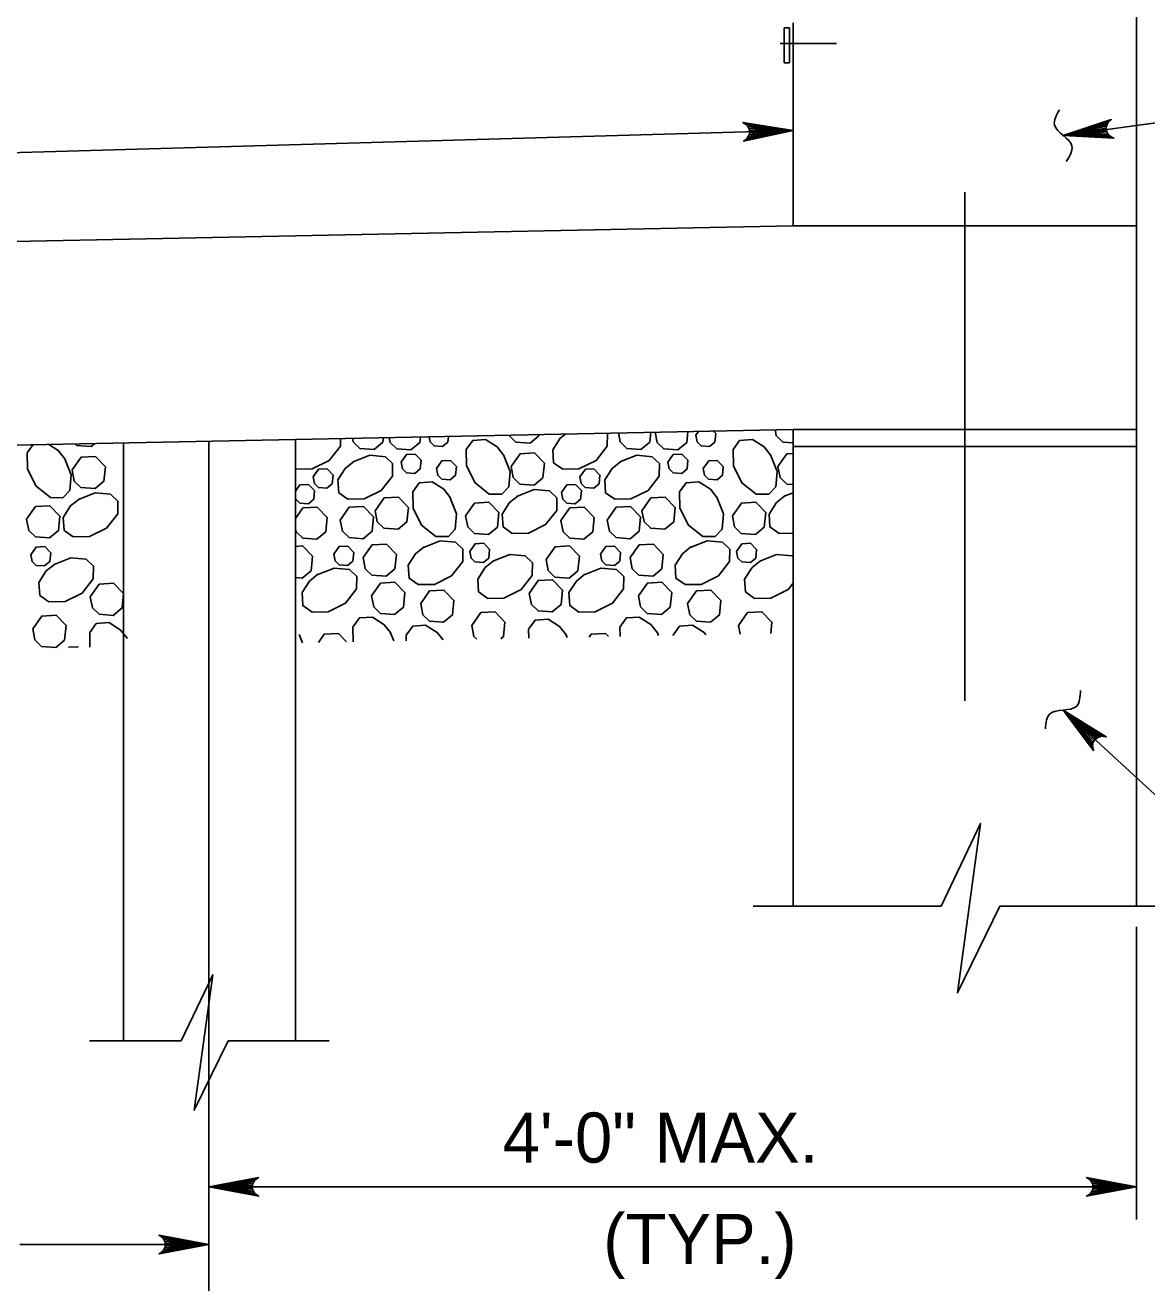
# Model space of a CAD drawing. Extents: x 636530 to 644067, y 294168 to 299122.
# Drawn here: x 638746.3 to 638813.5, y 294571.2 to 294647.1 of the extents above; entities that cross this region are included whole.
import ezdxf

# ---------------------------------------------------------------- set-up
doc = ezdxf.new("R2010")
doc.units = 0
doc.layers.add('1', color=7, linetype='Continuous')

msp = doc.modelspace()

# ---------------------------------------------------------------- linework, layer by layer
at = {"layer": '1'}
for p, q in [((638812.876, 294665.508), (638812.876, 294594.274)), ((638792.085, 294646.906), (638791.763, 294646.906)), ((638791.763, 294646.906), (638791.763, 294644.816)), ((638792.085, 294646.906), (638792.085, 294644.816)), ((638792.302, 294647.22), (638792.302, 294635.042)), ((638791.53, 294645.97), (638794.904, 294645.97)), ((638792.085, 294644.816), (638791.763, 294644.816)), ((638808.494, 294640.457), (638824.854, 294642.693)), ((638792.302, 294640.77), (638717.641, 294638.643)), ((638802.589, 294637.075), (638802.589, 294606.595)), ((638792.302, 294635.042), (638304.622, 294625.289)), ((638792.302, 294635.042), (638812.876, 294635.042)), ((638792.302, 294622.848), (638304.622, 294613.094)), ((638792.302, 294622.85), (638792.302, 294594.274)), ((638812.876, 294622.85), (638792.423, 294622.85)), ((638752.184, 294586.208), (638752.184, 294622.046)), ((638757.302, 294571.244), (638757.302, 294622.148)), ((638762.496, 294586.208), (638762.496, 294622.252)), ((638812.876, 294621.835), (638792.302, 294621.835)), ((638808.494, 294606.037), (638820.631, 294594.841)), ((638789.918, 294594.274), (638801.17, 294594.274)), ((638804.689, 294594.274), (638814.871, 294594.274)), ((638812.876, 294593.039), (638812.876, 294575.508)), ((638750.152, 294586.208), (638755.64, 294586.208)), ((638758.455, 294586.208), (638764.509, 294586.208)), ((638757.302, 294577.459), (638812.876, 294577.459)), ((638745.977, 294574.018), (638757.302, 294574.018))]:
    msp.add_line(p, q, dxfattribs=at)
for points in [[(638808.494, 294640.457), (638811.374, 294641.415), (638811.271, 294641.32), (638811.168, 294641.226), (638811.122, 294641.119), (638811.077, 294641.012), (638811.074, 294640.91), (638811.07, 294640.809), (638811.101, 294640.712), (638811.131, 294640.615), (638811.204, 294640.524), (638811.276, 294640.433), (638811.401, 294640.37), (638811.525, 294640.307), (638808.494, 294640.457), (638811.401, 294640.37), (638811.276, 294640.433), (638808.494, 294640.457), (638811.204, 294640.524), (638811.131, 294640.615), (638808.494, 294640.457), (638811.101, 294640.712), (638811.07, 294640.809), (638808.494, 294640.457), (638811.074, 294640.91), (638811.077, 294641.012), (638808.494, 294640.457), (638811.122, 294641.119), (638811.168, 294641.226), (638808.494, 294640.457), (638811.271, 294641.32)], [(638792.302, 294640.77), (638789.336, 294640.127), (638789.449, 294640.209), (638789.561, 294640.292), (638789.618, 294640.394), (638789.674, 294640.496), (638789.688, 294640.596), (638789.703, 294640.696), (638789.683, 294640.796), (638789.663, 294640.895), (638789.601, 294640.994), (638789.538, 294641.092), (638789.421, 294641.168), (638789.304, 294641.245), (638792.302, 294640.77), (638789.421, 294641.168), (638789.538, 294641.092), (638792.302, 294640.77), (638789.601, 294640.994), (638789.663, 294640.895), (638792.302, 294640.77), (638789.683, 294640.796), (638789.703, 294640.696), (638792.302, 294640.77), (638789.688, 294640.596), (638789.674, 294640.496), (638792.302, 294640.77), (638789.618, 294640.394), (638789.561, 294640.292), (638792.302, 294640.77), (638789.449, 294640.209)], [(638769.976, 294622.401), (638769.942, 294622.06), (638769.411, 294621.619), (638768.563, 294621.681), (638768.164, 294622.068), (638768.107, 294622.364)], [(638771.66, 294622.435), (638771.626, 294622.093), (638771.308, 294621.828), (638770.799, 294621.865), (638770.559, 294622.097), (638770.498, 294622.412)], [(638777.085, 294622.544), (638777.078, 294622.472), (638776.547, 294622.031), (638775.699, 294622.092), (638775.3, 294622.479), (638775.295, 294622.508)], [(638781.152, 294622.625), (638781.182, 294622.596), (638781.168, 294621.846), (638780.502, 294620.994), (638779.471, 294620.479), (638778.5, 294620.462), (638777.954, 294620.85), (638777.902, 294621.624), (638778.346, 294622.316), (638778.671, 294622.575)], [(638783.778, 294622.677), (638783.72, 294622.093), (638783.189, 294621.652), (638782.342, 294621.713), (638781.943, 294622.1), (638781.838, 294622.639)], [(638785.998, 294622.722), (638785.932, 294622.06), (638785.402, 294621.619), (638784.554, 294621.681), (638784.155, 294622.068), (638784.035, 294622.683)], [(638787.534, 294622.753), (638787.668, 294622.613), (638787.616, 294622.093), (638787.298, 294621.828), (638786.79, 294621.865), (638786.55, 294622.097), (638786.472, 294622.496)], [(638786.472, 294622.496), (638786.64, 294622.735)], [(638790.286, 294622.808), (638790.265, 294622.79), (638790.084, 294622.804)], [(638792.302, 294622.048), (638791.69, 294622.092), (638791.291, 294622.479), (638791.224, 294622.826)], [(638748.651, 294621.129), (638749.05, 294620.123), (638748.97, 294619.199), (638748.552, 294618.759), (638747.802, 294618.773), (638746.95, 294619.44), (638746.435, 294620.47), (638746.418, 294621.441), (638746.77, 294621.937)], [(638747.71, 294621.956), (638748.271, 294621.596), (638748.677, 294621.088)], [(638750.47, 294622.011), (638750.245, 294621.825), (638749.397, 294621.886), (638749.293, 294621.988)], [(638765.186, 294622.306), (638765.178, 294621.846), (638764.511, 294620.994), (638763.48, 294620.479), (638762.51, 294620.462), (638762.496, 294620.472)], [(638767.755, 294622.357), (638767.729, 294622.093), (638767.198, 294621.652), (638766.351, 294621.713), (638765.952, 294622.1), (638765.909, 294622.32)], [(638774.952, 294621.335), (638775.352, 294620.329), (638775.272, 294619.405), (638774.854, 294618.966), (638774.104, 294618.98), (638773.252, 294619.646), (638772.737, 294620.676), (638772.72, 294621.648), (638773.108, 294622.194), (638773.882, 294622.246), (638774.573, 294621.802), (638774.978, 294621.294)], [(638790.943, 294621.335), (638791.342, 294620.329), (638791.262, 294619.405), (638790.845, 294618.966), (638790.095, 294618.98), (638789.242, 294619.646), (638788.728, 294620.676), (638788.71, 294621.648), (638789.099, 294622.194), (638789.872, 294622.246), (638790.564, 294621.802), (638790.969, 294621.294)], [(638749.108, 294620.421), (638749.646, 294621.186), (638750.505, 294621.235), (638751.101, 294620.616), (638751.015, 294619.749), (638750.485, 294619.308), (638749.637, 294619.369), (638749.238, 294619.756), (638749.108, 294620.421)], [(638765.943, 294620.898), (638766.95, 294621.297), (638767.874, 294621.217), (638768.313, 294620.799), (638768.299, 294620.049), (638767.632, 294619.197), (638766.602, 294618.682), (638765.631, 294618.665), (638765.084, 294619.053), (638765.033, 294619.827), (638765.476, 294620.518), (638765.984, 294620.924)], [(638768.817, 294620.882), (638769.14, 294621.341), (638769.655, 294621.371), (638770.013, 294620.999), (638769.961, 294620.479), (638769.643, 294620.214), (638769.134, 294620.251), (638768.895, 294620.483), (638768.817, 294620.882)], [(638770.935, 294620.504), (638771.258, 294620.963), (638771.773, 294620.992), (638772.132, 294620.621), (638772.08, 294620.101), (638771.762, 294619.836), (638771.253, 294619.873), (638771.013, 294620.105), (638770.936, 294620.504)], [(638775.41, 294620.627), (638775.948, 294621.392), (638776.806, 294621.441), (638777.403, 294620.822), (638777.317, 294619.955), (638776.786, 294619.514), (638775.938, 294619.575), (638775.54, 294619.962), (638775.41, 294620.627)], [(638781.934, 294620.898), (638782.94, 294621.297), (638783.864, 294621.217), (638784.304, 294620.799), (638784.29, 294620.049), (638783.623, 294619.197), (638782.593, 294618.682), (638781.622, 294618.665), (638781.075, 294619.053), (638781.024, 294619.827), (638781.467, 294620.518), (638781.975, 294620.924)], [(638784.808, 294620.882), (638785.13, 294621.341), (638785.646, 294621.371), (638786.004, 294620.999), (638785.952, 294620.479), (638785.634, 294620.214), (638785.125, 294620.251), (638784.886, 294620.483), (638784.808, 294620.882)], [(638786.926, 294620.504), (638787.249, 294620.963), (638787.764, 294620.992), (638788.122, 294620.621), (638788.07, 294620.101), (638787.752, 294619.836), (638787.244, 294619.873), (638787.004, 294620.105), (638786.926, 294620.504)], [(638791.4, 294620.627), (638791.938, 294621.392), (638792.302, 294621.413)], [(638763.546, 294620), (638763.869, 294620.459), (638764.384, 294620.488), (638764.742, 294620.117), (638764.69, 294619.596), (638764.372, 294619.332), (638763.863, 294619.368), (638763.624, 294619.6), (638763.546, 294620)], [(638779.537, 294620), (638779.86, 294620.459), (638780.375, 294620.488), (638780.733, 294620.117), (638780.681, 294619.596), (638780.363, 294619.332), (638779.854, 294619.368), (638779.615, 294619.6), (638779.537, 294620)], [(638792.302, 294619.548), (638791.929, 294619.575), (638791.53, 294619.962), (638791.401, 294620.627)], [(638762.496, 294619.15), (638762.759, 294619.526), (638763.274, 294619.555), (638763.632, 294619.184), (638763.581, 294618.663), (638763.262, 294618.398), (638762.754, 294618.435), (638762.514, 294618.667), (638762.496, 294618.765)], [(638771.748, 294618.797), (638772.147, 294617.791), (638772.067, 294616.867), (638771.65, 294616.428), (638770.9, 294616.442), (638770.047, 294617.108), (638769.532, 294618.139), (638769.515, 294619.11), (638769.904, 294619.656), (638770.677, 294619.708), (638771.369, 294619.265), (638771.774, 294618.757)], [(638778.427, 294619.066), (638778.75, 294619.526), (638779.265, 294619.555), (638779.623, 294619.184), (638779.572, 294618.663), (638779.253, 294618.398), (638778.744, 294618.435), (638778.505, 294618.667), (638778.428, 294619.066)], [(638787.739, 294618.797), (638788.138, 294617.791), (638788.058, 294616.867), (638787.64, 294616.428), (638786.89, 294616.442), (638786.038, 294617.108), (638785.523, 294618.139), (638785.506, 294619.11), (638785.894, 294619.656), (638786.668, 294619.708), (638787.36, 294619.265), (638787.765, 294618.757)], [(638749.484, 294618.642), (638750.49, 294619.041), (638751.414, 294618.961), (638751.853, 294618.543), (638751.839, 294617.793), (638751.173, 294616.941), (638750.143, 294616.426), (638749.171, 294616.409), (638748.625, 294616.797), (638748.573, 294617.571), (638749.017, 294618.263), (638749.525, 294618.668)], [(638767.261, 294617.978), (638767.799, 294618.743), (638768.658, 294618.792), (638769.255, 294618.173), (638769.168, 294617.306), (638768.638, 294616.864), (638767.79, 294616.926), (638767.391, 294617.313), (638767.262, 294617.978)], [(638775.786, 294618.848), (638776.792, 294619.247), (638777.716, 294619.167), (638778.155, 294618.75), (638778.141, 294618), (638777.474, 294617.148), (638776.444, 294616.632), (638775.473, 294616.615), (638774.927, 294617.004), (638774.875, 294617.777), (638775.318, 294618.469), (638775.826, 294618.874)], [(638783.252, 294617.978), (638783.79, 294618.743), (638784.648, 294618.792), (638785.246, 294618.173), (638785.159, 294617.306), (638784.628, 294616.864), (638783.781, 294616.926), (638783.382, 294617.313), (638783.252, 294617.978)], [(638792.302, 294616.63), (638791.464, 294616.615), (638790.918, 294617.004), (638790.866, 294617.777), (638791.309, 294618.469), (638791.817, 294618.874)], [(638791.776, 294618.848), (638792.302, 294619.057)], [(638746.382, 294617.463), (638746.92, 294618.228), (638747.779, 294618.277), (638748.376, 294617.658), (638748.289, 294616.791), (638747.759, 294616.349), (638746.911, 294616.411), (638746.512, 294616.797), (638746.383, 294617.463)], [(638762.496, 294617.52), (638762.938, 294618.15), (638763.797, 294618.199), (638764.394, 294617.58), (638764.308, 294616.713), (638763.777, 294616.272), (638762.929, 294616.333), (638762.53, 294616.72), (638762.496, 294616.9)], [(638765.175, 294617.417), (638765.713, 294618.182), (638766.572, 294618.231), (638767.169, 294617.612), (638767.082, 294616.744), (638766.552, 294616.303), (638765.704, 294616.365), (638765.305, 294616.752), (638765.176, 294617.416)], [(638772.684, 294617.669), (638773.222, 294618.434), (638774.081, 294618.483), (638774.678, 294617.864), (638774.591, 294616.997), (638774.061, 294616.556), (638773.213, 294616.617), (638772.814, 294617.004), (638772.685, 294617.669)], [(638778.391, 294617.385), (638778.929, 294618.15), (638779.788, 294618.199), (638780.385, 294617.58), (638780.298, 294616.713), (638779.768, 294616.272), (638778.92, 294616.333), (638778.521, 294616.72), (638778.392, 294617.385)], [(638781.166, 294617.417), (638781.704, 294618.182), (638782.563, 294618.231), (638783.16, 294617.612), (638783.073, 294616.744), (638782.543, 294616.303), (638781.695, 294616.365), (638781.296, 294616.752), (638781.167, 294617.416)], [(638788.675, 294617.669), (638789.213, 294618.434), (638790.072, 294618.483), (638790.668, 294617.864), (638790.582, 294616.997), (638790.052, 294616.556), (638789.204, 294616.617), (638788.805, 294617.004), (638788.676, 294617.669)], [(638746.627, 294615.337), (638746.95, 294615.797), (638747.465, 294615.826), (638747.823, 294615.455), (638747.772, 294614.934), (638747.453, 294614.669), (638746.945, 294614.706), (638746.705, 294614.939), (638746.628, 294615.337)], [(638762.496, 294615.843), (638762.915, 294615.867), (638763.512, 294615.248), (638763.426, 294614.38), (638762.895, 294613.939), (638762.496, 294613.968)], [(638764.782, 294615.367), (638765.104, 294615.826), (638765.62, 294615.856), (638765.978, 294615.484), (638765.926, 294614.964), (638765.608, 294614.699), (638765.099, 294614.736), (638764.86, 294614.968), (638764.782, 294615.367)], [(638766.544, 294615.169), (638767.082, 294615.934), (638767.941, 294615.983), (638768.538, 294615.364), (638768.451, 294614.497), (638767.921, 294614.056), (638767.073, 294614.117), (638766.674, 294614.504), (638766.545, 294615.169)], [(638770.153, 294615.78), (638771.16, 294616.179), (638772.084, 294616.1), (638772.523, 294615.682), (638772.509, 294614.932), (638771.842, 294614.08), (638770.812, 294613.564), (638769.841, 294613.548), (638769.294, 294613.936), (638769.242, 294614.709), (638769.686, 294615.401), (638770.194, 294615.806)], [(638772.929, 294615.544), (638773.252, 294616.003), (638773.767, 294616.032), (638774.125, 294615.661), (638774.074, 294615.14), (638773.755, 294614.876), (638773.246, 294614.912), (638773.007, 294615.145), (638772.93, 294615.544)], [(638777.509, 294615.052), (638778.047, 294615.818), (638778.906, 294615.867), (638779.503, 294615.248), (638779.416, 294614.38), (638778.886, 294613.939), (638778.038, 294614.001), (638777.639, 294614.388), (638777.51, 294615.052)], [(638780.772, 294615.367), (638781.095, 294615.826), (638781.61, 294615.856), (638781.969, 294615.484), (638781.917, 294614.964), (638781.599, 294614.699), (638781.09, 294614.736), (638780.85, 294614.968), (638780.773, 294615.367)], [(638782.535, 294615.169), (638783.073, 294615.934), (638783.932, 294615.983), (638784.528, 294615.364), (638784.442, 294614.497), (638783.912, 294614.056), (638783.064, 294614.117), (638782.665, 294614.504), (638782.536, 294615.169)], [(638786.144, 294615.78), (638787.15, 294616.179), (638788.074, 294616.1), (638788.514, 294615.682), (638788.5, 294614.932), (638787.833, 294614.08), (638786.803, 294613.564), (638785.832, 294613.548), (638785.285, 294613.936), (638785.233, 294614.709), (638785.677, 294615.401), (638786.185, 294615.806)], [(638788.92, 294615.544), (638789.243, 294616.003), (638789.758, 294616.032), (638790.116, 294615.661), (638790.064, 294615.14), (638789.746, 294614.876), (638789.237, 294614.912), (638788.998, 294615.145), (638788.92, 294615.544)], [(638748.021, 294614.748), (638749.027, 294615.147), (638749.951, 294615.067), (638750.391, 294614.65), (638750.377, 294613.9), (638749.71, 294613.047), (638748.68, 294612.532), (638747.709, 294612.515), (638747.162, 294612.904), (638747.11, 294613.677), (638747.554, 294614.369), (638748.062, 294614.774)], [(638774.323, 294614.954), (638775.329, 294615.353), (638776.253, 294615.274), (638776.692, 294614.856), (638776.678, 294614.106), (638776.012, 294613.254), (638774.982, 294612.738), (638774.01, 294612.722), (638773.464, 294613.11), (638773.412, 294613.883), (638773.856, 294614.575), (638774.364, 294614.98)], [(638792.302, 294613.636), (638792.002, 294613.254), (638790.972, 294612.738), (638790.001, 294612.722), (638789.455, 294613.11), (638789.403, 294613.883), (638789.846, 294614.575), (638790.354, 294614.98)], [(638790.314, 294614.954), (638791.32, 294615.353), (638792.244, 294615.274), (638792.302, 294615.219)], [(638763.798, 294614.141), (638764.804, 294614.54), (638765.728, 294614.46), (638766.168, 294614.042), (638766.154, 294613.292), (638765.487, 294612.44), (638764.456, 294611.925), (638763.486, 294611.908), (638762.939, 294612.296), (638762.887, 294613.07), (638763.331, 294613.762), (638763.839, 294614.167)], [(638779.789, 294614.141), (638780.795, 294614.54), (638781.719, 294614.46), (638782.158, 294614.042), (638782.144, 294613.292), (638781.478, 294612.44), (638780.447, 294611.925), (638779.476, 294611.908), (638778.93, 294612.296), (638778.878, 294613.07), (638779.322, 294613.762), (638779.83, 294614.167)], [(638750.195, 294612.822), (638750.733, 294613.587), (638751.592, 294613.637), (638752.189, 294613.017), (638752.103, 294612.15), (638751.572, 294611.709), (638750.724, 294611.771), (638750.325, 294612.157), (638750.196, 294612.822)], [(638767.05, 294612.878), (638767.588, 294613.644), (638768.447, 294613.692), (638769.044, 294613.074), (638768.957, 294612.206), (638768.427, 294611.765), (638767.579, 294611.826), (638767.18, 294612.213), (638767.051, 294612.878)], [(638776.497, 294613.028), (638777.035, 294613.794), (638777.894, 294613.843), (638778.491, 294613.224), (638778.404, 294612.356), (638777.874, 294611.915), (638777.026, 294611.977), (638776.627, 294612.364), (638776.498, 294613.028)], [(638783.041, 294612.878), (638783.579, 294613.644), (638784.438, 294613.692), (638785.034, 294613.074), (638784.948, 294612.206), (638784.418, 294611.765), (638783.57, 294611.826), (638783.171, 294612.213), (638783.042, 294612.878)], [(638769.991, 294612.41), (638770.528, 294613.175), (638771.387, 294613.224), (638771.984, 294612.605), (638771.898, 294611.738), (638771.367, 294611.296), (638770.52, 294611.358), (638770.121, 294611.745), (638769.991, 294612.41)], [(638785.982, 294612.41), (638786.519, 294613.175), (638787.378, 294613.224), (638787.975, 294612.605), (638787.888, 294611.738), (638787.358, 294611.296), (638786.51, 294611.358), (638786.112, 294611.745), (638785.982, 294612.41)], [(638773.048, 294611.109), (638773.586, 294611.874), (638774.445, 294611.923), (638775.042, 294611.304), (638774.956, 294610.437), (638774.795, 294610.303)], [(638789.039, 294611.109), (638789.577, 294611.874), (638790.436, 294611.923), (638791.033, 294611.304), (638790.965, 294610.627)], [(638746.747, 294610.903), (638747.285, 294611.668), (638748.143, 294611.717), (638748.74, 294611.098), (638748.654, 294610.231), (638748.123, 294609.789), (638747.275, 294609.851), (638746.877, 294610.238), (638746.747, 294610.903)], [(638750.175, 294609.811), (638750.159, 294610.675), (638750.548, 294611.221), (638751.321, 294611.273), (638752.013, 294610.83), (638752.418, 294610.322)], [(638765.952, 294610.127), (638765.936, 294611.011), (638766.325, 294611.558), (638767.098, 294611.61), (638767.79, 294611.166), (638768.195, 294610.658)], [(638769.131, 294610.19), (638769.125, 294610.523), (638769.514, 294611.07), (638770.287, 294611.122), (638770.979, 294610.678), (638771.333, 294610.234)], [(638773.353, 294610.275), (638773.178, 294610.444), (638773.049, 294611.109)], [(638776.471, 294610.337), (638776.461, 294610.881), (638776.85, 294611.428), (638777.623, 294611.479), (638778.315, 294611.036), (638778.72, 294610.528)], [(638781.937, 294610.446), (638781.927, 294611.011), (638782.316, 294611.558), (638783.089, 294611.61), (638783.781, 294611.166), (638784.186, 294610.658)], [(638785.116, 294610.51), (638785.116, 294610.523), (638785.504, 294611.07), (638786.278, 294611.122), (638786.97, 294610.678), (638787.073, 294610.549)], [(638789.141, 294610.59), (638789.04, 294611.109)], [(638762.703, 294610.569), (638762.903, 294610.066)], [(638763.864, 294610.085), (638764.207, 294610.573), (638765.066, 294610.622), (638765.552, 294610.119)], [(638768.17, 294610.699), (638768.377, 294610.175)], [(638778.694, 294610.569), (638778.768, 294610.383)], [(638780.083, 294610.409), (638780.198, 294610.573), (638781.057, 294610.622), (638781.24, 294610.432)], [(638784.16, 294610.699), (638784.242, 294610.492)], [(638748.911, 294609.786), (638748.917, 294609.794), (638749.433, 294609.824), (638749.459, 294609.797)], [(638808.494, 294606.037), (638810.308, 294603.604), (638810.277, 294603.74), (638810.247, 294603.876), (638810.271, 294603.99), (638810.295, 294604.104), (638810.35, 294604.189), (638810.405, 294604.274), (638810.486, 294604.336), (638810.566, 294604.398), (638810.678, 294604.431), (638810.789, 294604.464), (638810.927, 294604.445), (638811.066, 294604.426), (638808.494, 294606.037), (638810.927, 294604.445), (638810.789, 294604.464), (638808.494, 294606.037), (638810.678, 294604.431), (638810.566, 294604.398), (638808.494, 294606.037), (638810.486, 294604.336), (638810.405, 294604.274), (638808.494, 294606.037), (638810.35, 294604.189), (638810.295, 294604.104), (638808.494, 294606.037), (638810.271, 294603.99), (638810.247, 294603.876), (638808.494, 294606.037), (638810.277, 294603.74)], [(638804.689, 294594.274), (638802.151, 294589.089), (638803.531, 294599.238), (638801.17, 294594.274)], [(638758.455, 294586.208), (638756.425, 294582.059), (638757.529, 294590.178), (638755.64, 294586.208)], [(638757.302, 294577.459), (638760.284, 294578.022), (638760.169, 294577.942), (638760.054, 294577.863), (638759.995, 294577.763), (638759.936, 294577.663), (638759.919, 294577.562), (638759.902, 294577.462), (638759.919, 294577.362), (638759.936, 294577.263), (638759.996, 294577.163), (638760.055, 294577.063), (638760.17, 294576.983), (638760.285, 294576.904), (638757.302, 294577.459), (638760.17, 294576.983), (638760.055, 294577.063), (638757.302, 294577.459), (638759.996, 294577.163), (638759.936, 294577.263), (638757.302, 294577.459), (638759.919, 294577.362), (638759.902, 294577.462), (638757.302, 294577.459), (638759.919, 294577.562), (638759.936, 294577.663), (638757.302, 294577.459), (638759.995, 294577.763), (638760.054, 294577.863), (638757.302, 294577.459), (638760.169, 294577.942)], [(638812.876, 294577.459), (638809.894, 294578.022), (638810.008, 294577.942), (638810.123, 294577.863), (638810.182, 294577.763), (638810.241, 294577.663), (638810.258, 294577.562), (638810.276, 294577.462), (638810.258, 294577.362), (638810.241, 294577.263), (638810.182, 294577.163), (638810.122, 294577.063), (638810.007, 294576.983), (638809.892, 294576.904), (638812.876, 294577.459), (638810.007, 294576.983), (638810.122, 294577.063), (638812.876, 294577.459), (638810.182, 294577.163), (638810.241, 294577.263), (638812.876, 294577.459), (638810.258, 294577.362), (638810.276, 294577.462), (638812.876, 294577.459), (638810.258, 294577.562), (638810.241, 294577.663), (638812.876, 294577.459), (638810.182, 294577.763), (638810.123, 294577.863), (638812.876, 294577.459), (638810.008, 294577.942)], [(638757.302, 294574.018), (638754.321, 294573.447), (638754.436, 294573.527), (638754.55, 294573.607), (638754.609, 294573.708), (638754.668, 294573.808), (638754.685, 294573.908), (638754.702, 294574.008), (638754.684, 294574.108), (638754.667, 294574.208), (638754.607, 294574.308), (638754.547, 294574.407), (638754.432, 294574.487), (638754.317, 294574.566), (638757.302, 294574.018), (638754.432, 294574.487), (638754.547, 294574.407), (638757.302, 294574.018), (638754.607, 294574.308), (638754.667, 294574.208), (638757.302, 294574.018), (638754.684, 294574.108), (638754.702, 294574.008), (638757.302, 294574.018), (638754.685, 294573.908), (638754.668, 294573.808), (638757.302, 294574.018), (638754.609, 294573.708), (638754.55, 294573.607), (638757.302, 294574.018), (638754.436, 294573.527)]]:
    msp.add_lwpolyline(points, dxfattribs=at)
msp.add_lwpolyline([(638792.302, 294622.85), (638812.876, 294622.85), (638812.876, 294621.835), (638792.302, 294621.835)], close=True, dxfattribs=at)
for points in [[(638808.673, 294638.908), (638809.014, 294639.826), (638807.969, 294641.095), (638808.263, 294641.994)], [(638809.528, 294607.205), (638809.282, 294606.257), (638807.698, 294605.814), (638807.425, 294604.908)]]:
    msp.add_spline(points, degree=3, dxfattribs=at)

# ---------------------------------------------------------------- texts
for s, p in [('4\'-0" MAX.', (638774.905, 294578.918)), ('(TYP.)', (638780.928, 294572.846))]:
    msp.add_text(s, height=3, rotation=360, dxfattribs=at).set_placement(p)

doc.saveas('drawing.dxf')
